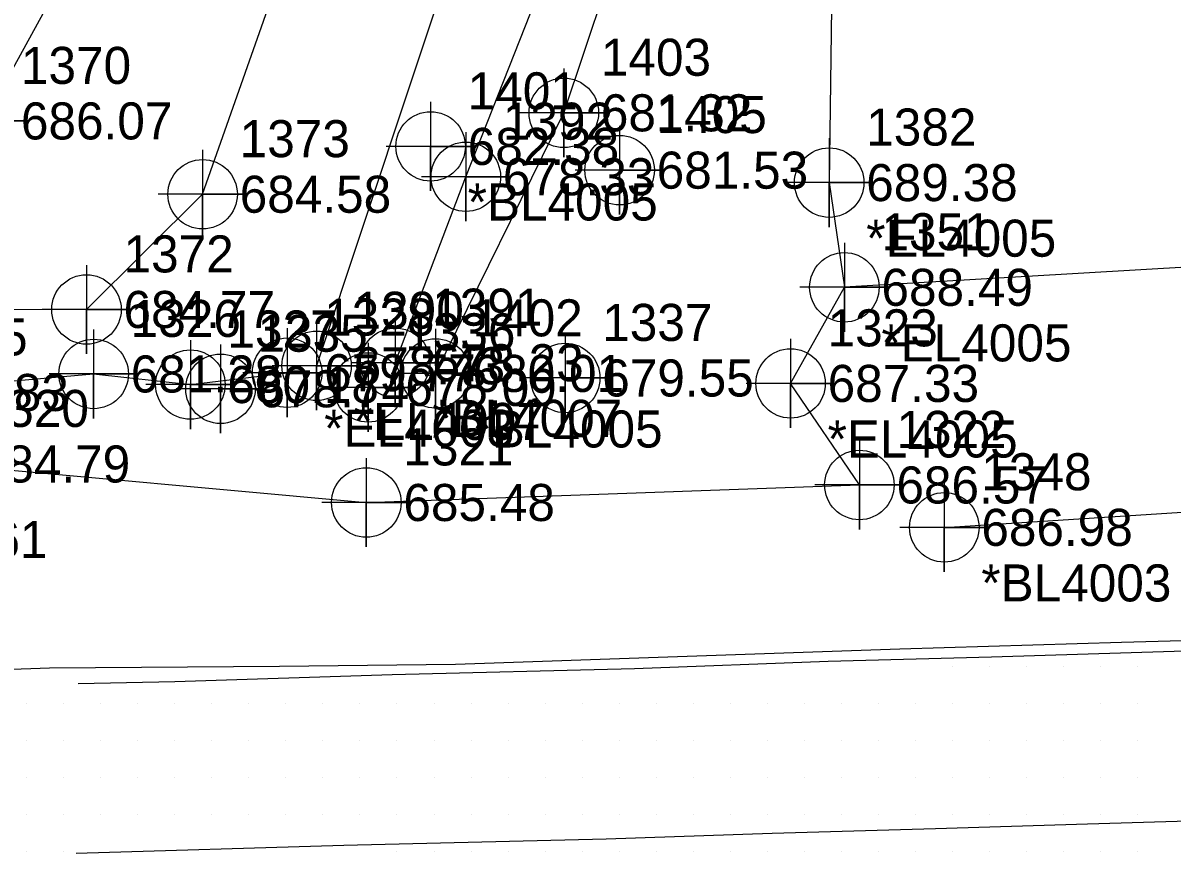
# Model space of a CAD drawing. Extents: x 1755643 to 1760494, y 736519 to 737621.
# Drawn here: x 1759066 to 1759143.6, y 737021.1 to 737077.2 of the extents above; entities that cross this region are included whole.
import ezdxf

# ---------------------------------------------------------------- set-up
doc = ezdxf.new("R2010")
doc.units = 0
for name, color, linetype in [('Exist Horizontal Alignment Curve and Spiral Data', 7, 'Continuous'), ('Exist Horizontal Alignment Direction Label', 7, 'Continuous'), ('Exist Roads EOT', 7, 'Continuous'), ('Exist Utilities Sanitary Sewer UG Line', 7, 'Continuous'), ('Old_Level_1', 7, 'Continuous'), ('Old_Level_10', 7, 'Continuous'), ('Old_Level_2', 7, 'Continuous'), ('Old_Level_3', 7, 'Continuous'), ('Prop Conc 5in Monolithic Keyed In Island', 7, 'Continuous'), ('Prop Dimension', 7, 'Continuous'), ('Prop EOT Dash', 7, 'Continuous'), ('Prop Horizontal Alignment Direction Label', 7, 'Continuous'), ('Prop Horizontal Alignment Station Label', 7, 'Continuous'), ('Prop Horizontal Alignment Tick Label', 7, 'Continuous'), ('Prop Horizontal Alignment Tick Large', 7, 'Continuous'), ('Prop Horizontal Alignment Tick Small', 7, 'Continuous'), ('Prop Lane Lines', 7, 'Continuous'), ('Prop Paved Shoulder', 7, 'Continuous'), ('Prop Superelevation Label', 7, 'Continuous'), ('Prop Terminator CELL', 7, 'Continuous'), ('Scratch_Level_1', 7, 'Continuous'), ('Scratch_Level_2', 7, 'Continuous'), ('Scratch_Level_5', 7, 'Continuous'), ('Scratch_Level_9', 7, 'Continuous')]:
    doc.layers.add(name, color=color, linetype=linetype)

msp = doc.modelspace()

# ---------------------------------------------------------------- linework, layer by layer
at = {"layer": 'Exist Horizontal Alignment Curve and Spiral Data'}
for points in [[(1759106.275, 737070.227), (1759106.275, 737064.227), (1759106.275, 737067.227), (1759109.275, 737067.227), (1759103.275, 737067.227)], [(1759102.603, 737056.204), (1759102.603, 737050.204), (1759102.603, 737053.204), (1759105.603, 737053.204), (1759099.603, 737053.204)], [(1759079.336, 737055.474), (1759079.336, 737049.474), (1759079.336, 737052.474), (1759082.336, 737052.474), (1759076.336, 737052.474)]]:
    msp.add_lwpolyline(points, dxfattribs=at)
for centre in [(1759106.275, 737067.227), (1759102.603, 737053.204), (1759079.336, 737052.474)]:
    msp.add_circle(centre, 2.344, dxfattribs=at)
at = {"layer": 'Old_Level_10'}
for points in [[(1759070.776, 737056.475), (1759070.776, 737050.475), (1759070.776, 737053.475), (1759073.776, 737053.475), (1759067.776, 737053.475)], [(1759083.837, 737056.56), (1759083.837, 737050.56), (1759083.837, 737053.56), (1759086.837, 737053.56), (1759080.837, 737053.56)], [(1759077.303, 737055.758), (1759077.303, 737049.758), (1759077.303, 737052.758), (1759080.303, 737052.758), (1759074.303, 737052.758)], [(1759128.188, 737046.125), (1759128.188, 737040.125), (1759128.188, 737043.125), (1759131.188, 737043.125), (1759125.188, 737043.125)]]:
    msp.add_lwpolyline(points, dxfattribs=at)
for centre in [(1759070.776, 737053.475), (1759083.837, 737053.56), (1759077.303, 737052.758), (1759128.188, 737043.125)]:
    msp.add_circle(centre, 2.344, dxfattribs=at)
at = {"layer": 'Prop Dimension'}
msp.add_line((1759128.188, 737043.125), (1759176.605, 737046.242), dxfattribs=at)
msp.add_lwpolyline([(1759031.302, 737046.485), (1759056.382, 737052.226), (1759070.776, 737053.475), (1759077.303, 737052.758), (1759083.837, 737053.56)], dxfattribs=at)
at = {"layer": 'Prop Horizontal Alignment Station Label'}
msp.add_lwpolyline([(1759089.307, 737055.567), (1759089.307, 737049.567), (1759089.307, 737052.567), (1759092.307, 737052.567), (1759086.307, 737052.567)], dxfattribs=at)
msp.add_circle((1759089.307, 737052.567), 2.344, dxfattribs=at)
at = {"layer": 'Prop Horizontal Alignment Tick Small'}
for points in [[(1759095.896, 737069.783), (1759095.896, 737063.783), (1759095.896, 737066.783), (1759098.896, 737066.783), (1759092.896, 737066.783)], [(1759085.823, 737057.025), (1759085.823, 737051.025), (1759085.823, 737054.025), (1759088.823, 737054.025), (1759082.823, 737054.025)], [(1759091.129, 737057.232), (1759091.129, 737051.232), (1759091.129, 737054.232), (1759094.129, 737054.232), (1759088.129, 737054.232)]]:
    msp.add_lwpolyline(points, dxfattribs=at)
for centre in [(1759095.896, 737066.783), (1759085.823, 737054.025), (1759091.129, 737054.232)]:
    msp.add_circle(centre, 2.344, dxfattribs=at)
at = {"layer": 'Prop Lane Lines'}
for points in [[(1759102.509, 737074.095), (1759102.509, 737068.095), (1759102.509, 737071.095), (1759105.509, 737071.095), (1759099.509, 737071.095)], [(1759063.368, 737073.548), (1759063.368, 737067.548), (1759063.368, 737070.548), (1759066.368, 737070.548), (1759060.368, 737070.548)], [(1759093.521, 737071.829), (1759093.521, 737065.829), (1759093.521, 737068.829), (1759096.521, 737068.829), (1759090.521, 737068.829)], [(1759120.419, 737069.387), (1759120.419, 737063.387), (1759120.419, 737066.387), (1759123.419, 737066.387), (1759117.419, 737066.387)], [(1759078.132, 737068.603), (1759078.132, 737062.603), (1759078.132, 737065.603), (1759081.132, 737065.603), (1759075.132, 737065.603)], [(1759121.445, 737062.322), (1759121.445, 737056.322), (1759121.445, 737059.322), (1759124.445, 737059.322), (1759118.445, 737059.322)], [(1759070.291, 737060.826), (1759070.291, 737054.826), (1759070.291, 737057.826), (1759073.291, 737057.826), (1759067.291, 737057.826)], [(1759093.85, 737056.511), (1759093.85, 737050.511), (1759093.85, 737053.511), (1759096.85, 737053.511), (1759090.85, 737053.511)], [(1759117.814, 737055.836), (1759117.814, 737049.836), (1759117.814, 737052.836), (1759120.814, 737052.836), (1759114.814, 737052.836)], [(1759122.458, 737048.984), (1759122.458, 737042.984), (1759122.458, 737045.984), (1759125.458, 737045.984), (1759119.458, 737045.984)], [(1759089.18, 737047.802), (1759089.18, 737041.802), (1759089.18, 737044.802), (1759092.18, 737044.802), (1759086.18, 737044.802)]]:
    msp.add_lwpolyline(points, dxfattribs=at)
for centre in [(1759102.509, 737071.095), (1759093.521, 737068.829), (1759120.419, 737066.387), (1759078.132, 737065.603), (1759121.445, 737059.322), (1759070.291, 737057.826), (1759093.85, 737053.511), (1759117.814, 737052.836), (1759122.458, 737045.984), (1759089.18, 737044.802)]:
    msp.add_circle(centre, 2.344, dxfattribs=at)
at = {"layer": 'Prop Terminator CELL'}
for points in [[(1759091.129, 737054.232), (1759095.896, 737066.783), (1759106.108, 737092.633), (1759116.257, 737109.006), (1759126.282, 737133.12), (1759139.374, 737163.771)], [(1759129.426, 737158.51), (1759116.04, 737134.286), (1759110.504, 737114.906), (1759098.55, 737092.322), (1759085.823, 737054.025)]]:
    msp.add_lwpolyline(points, dxfattribs=at)
at = {"layer": 'Scratch_Level_1'}
msp.add_lwpolyline([(1759245.745, 737039.347), (1759243.901, 737039.092), (1759228.947, 737038.55), (1759213.991, 737037.986), (1759199.029, 737037.383), (1759184.081, 737036.787), (1759169.113, 737036.293), (1759154.142, 737035.742), (1759140.158, 737035.361), (1759125.179, 737034.912), (1759110.187, 737034.391), (1759095.208, 737033.867), (1759083.321, 737033.73), (1759067.799, 737033.624), (1759060.797, 737033.37)], dxfattribs=at)
at = {"layer": 'Scratch_Level_2'}
for p, q in [((1759128.75, 737033.75), (1759128.75, 737033.75)), ((1759131.25, 737033.75), (1759131.25, 737033.75)), ((1759133.75, 737033.75), (1759133.75, 737033.75)), ((1759136.25, 737033.75), (1759136.25, 737033.75)), ((1759138.75, 737033.75), (1759138.75, 737033.75)), ((1759141.25, 737033.75), (1759141.25, 737033.75)), ((1759066.25, 737031.25), (1759066.25, 737031.25)), ((1759068.75, 737031.25), (1759068.75, 737031.25)), ((1759071.25, 737031.25), (1759071.25, 737031.25)), ((1759073.75, 737031.25), (1759073.75, 737031.25)), ((1759076.25, 737031.25), (1759076.25, 737031.25)), ((1759078.75, 737031.25), (1759078.75, 737031.25)), ((1759081.25, 737031.25), (1759081.25, 737031.25)), ((1759083.75, 737031.25), (1759083.75, 737031.25)), ((1759086.25, 737031.25), (1759086.25, 737031.25)), ((1759088.75, 737031.25), (1759088.75, 737031.25)), ((1759091.25, 737031.25), (1759091.25, 737031.25)), ((1759093.75, 737031.25), (1759093.75, 737031.25)), ((1759096.25, 737031.25), (1759096.25, 737031.25)), ((1759098.75, 737031.25), (1759098.75, 737031.25)), ((1759101.25, 737031.25), (1759101.25, 737031.25)), ((1759103.75, 737031.25), (1759103.75, 737031.25)), ((1759106.25, 737031.25), (1759106.25, 737031.25)), ((1759108.75, 737031.25), (1759108.75, 737031.25)), ((1759111.25, 737031.25), (1759111.25, 737031.25)), ((1759113.75, 737031.25), (1759113.75, 737031.25)), ((1759116.25, 737031.25), (1759116.25, 737031.25)), ((1759118.75, 737031.25), (1759118.75, 737031.25)), ((1759121.25, 737031.25), (1759121.25, 737031.25)), ((1759123.75, 737031.25), (1759123.75, 737031.25)), ((1759126.25, 737031.25), (1759126.25, 737031.25)), ((1759128.75, 737031.25), (1759128.75, 737031.25)), ((1759131.25, 737031.25), (1759131.25, 737031.25)), ((1759133.75, 737031.25), (1759133.75, 737031.25)), ((1759136.25, 737031.25), (1759136.25, 737031.25)), ((1759138.75, 737031.25), (1759138.75, 737031.25)), ((1759141.25, 737031.25), (1759141.25, 737031.25)), ((1759066.25, 737028.75), (1759066.25, 737028.75)), ((1759068.75, 737028.75), (1759068.75, 737028.75)), ((1759071.25, 737028.75), (1759071.25, 737028.75)), ((1759073.75, 737028.75), (1759073.75, 737028.75)), ((1759076.25, 737028.75), (1759076.25, 737028.75)), ((1759078.75, 737028.75), (1759078.75, 737028.75)), ((1759081.25, 737028.75), (1759081.25, 737028.75)), ((1759083.75, 737028.75), (1759083.75, 737028.75)), ((1759086.25, 737028.75), (1759086.25, 737028.75)), ((1759088.75, 737028.75), (1759088.75, 737028.75)), ((1759091.25, 737028.75), (1759091.25, 737028.75)), ((1759093.75, 737028.75), (1759093.75, 737028.75)), ((1759096.25, 737028.75), (1759096.25, 737028.75)), ((1759098.75, 737028.75), (1759098.75, 737028.75)), ((1759101.25, 737028.75), (1759101.25, 737028.75)), ((1759103.75, 737028.75), (1759103.75, 737028.75)), ((1759106.25, 737028.75), (1759106.25, 737028.75)), ((1759108.75, 737028.75), (1759108.75, 737028.75)), ((1759111.25, 737028.75), (1759111.25, 737028.75)), ((1759113.75, 737028.75), (1759113.75, 737028.75)), ((1759116.25, 737028.75), (1759116.25, 737028.75)), ((1759118.75, 737028.75), (1759118.75, 737028.75)), ((1759121.25, 737028.75), (1759121.25, 737028.75)), ((1759123.75, 737028.75), (1759123.75, 737028.75)), ((1759126.25, 737028.75), (1759126.25, 737028.75)), ((1759128.75, 737028.75), (1759128.75, 737028.75)), ((1759131.25, 737028.75), (1759131.25, 737028.75)), ((1759133.75, 737028.75), (1759133.75, 737028.75)), ((1759136.25, 737028.75), (1759136.25, 737028.75)), ((1759138.75, 737028.75), (1759138.75, 737028.75)), ((1759141.25, 737028.75), (1759141.25, 737028.75)), ((1759066.25, 737026.25), (1759066.25, 737026.25)), ((1759068.75, 737026.25), (1759068.75, 737026.25)), ((1759071.25, 737026.25), (1759071.25, 737026.25)), ((1759073.75, 737026.25), (1759073.75, 737026.25)), ((1759076.25, 737026.25), (1759076.25, 737026.25)), ((1759078.75, 737026.25), (1759078.75, 737026.25)), ((1759081.25, 737026.25), (1759081.25, 737026.25)), ((1759083.75, 737026.25), (1759083.75, 737026.25)), ((1759086.25, 737026.25), (1759086.25, 737026.25)), ((1759088.75, 737026.25), (1759088.75, 737026.25)), ((1759091.25, 737026.25), (1759091.25, 737026.25)), ((1759093.75, 737026.25), (1759093.75, 737026.25)), ((1759096.25, 737026.25), (1759096.25, 737026.25)), ((1759098.75, 737026.25), (1759098.75, 737026.25)), ((1759101.25, 737026.25), (1759101.25, 737026.25)), ((1759103.75, 737026.25), (1759103.75, 737026.25)), ((1759106.25, 737026.25), (1759106.25, 737026.25)), ((1759108.75, 737026.25), (1759108.75, 737026.25)), ((1759111.25, 737026.25), (1759111.25, 737026.25)), ((1759113.75, 737026.25), (1759113.75, 737026.25)), ((1759116.25, 737026.25), (1759116.25, 737026.25)), ((1759118.75, 737026.25), (1759118.75, 737026.25)), ((1759121.25, 737026.25), (1759121.25, 737026.25)), ((1759123.75, 737026.25), (1759123.75, 737026.25)), ((1759126.25, 737026.25), (1759126.25, 737026.25)), ((1759128.75, 737026.25), (1759128.75, 737026.25)), ((1759131.25, 737026.25), (1759131.25, 737026.25)), ((1759133.75, 737026.25), (1759133.75, 737026.25)), ((1759136.25, 737026.25), (1759136.25, 737026.25)), ((1759138.75, 737026.25), (1759138.75, 737026.25)), ((1759141.25, 737026.25), (1759141.25, 737026.25)), ((1759066.25, 737023.75), (1759066.25, 737023.75)), ((1759068.75, 737023.75), (1759068.75, 737023.75)), ((1759071.25, 737023.75), (1759071.25, 737023.75)), ((1759073.75, 737023.75), (1759073.75, 737023.75)), ((1759076.25, 737023.75), (1759076.25, 737023.75)), ((1759078.75, 737023.75), (1759078.75, 737023.75)), ((1759081.25, 737023.75), (1759081.25, 737023.75)), ((1759083.75, 737023.75), (1759083.75, 737023.75)), ((1759086.25, 737023.75), (1759086.25, 737023.75)), ((1759088.75, 737023.75), (1759088.75, 737023.75)), ((1759091.25, 737023.75), (1759091.25, 737023.75)), ((1759093.75, 737023.75), (1759093.75, 737023.75)), ((1759096.25, 737023.75), (1759096.25, 737023.75)), ((1759098.75, 737023.75), (1759098.75, 737023.75)), ((1759101.25, 737023.75), (1759101.25, 737023.75)), ((1759103.75, 737023.75), (1759103.75, 737023.75)), ((1759106.25, 737023.75), (1759106.25, 737023.75)), ((1759108.75, 737023.75), (1759108.75, 737023.75)), ((1759111.25, 737023.75), (1759111.25, 737023.75)), ((1759113.75, 737023.75), (1759113.75, 737023.75)), ((1759116.25, 737023.75), (1759116.25, 737023.75)), ((1759118.75, 737023.75), (1759118.75, 737023.75)), ((1759121.25, 737023.75), (1759121.25, 737023.75)), ((1759123.75, 737023.75), (1759123.75, 737023.75)), ((1759126.25, 737023.75), (1759126.25, 737023.75)), ((1759128.75, 737023.75), (1759128.75, 737023.75)), ((1759131.25, 737023.75), (1759131.25, 737023.75)), ((1759133.75, 737023.75), (1759133.75, 737023.75)), ((1759136.25, 737023.75), (1759136.25, 737023.75)), ((1759138.75, 737023.75), (1759138.75, 737023.75)), ((1759141.25, 737023.75), (1759141.25, 737023.75)), ((1759066.25, 737021.25), (1759066.25, 737021.25)), ((1759068.75, 737021.25), (1759068.75, 737021.25)), ((1759091.25, 737021.25), (1759091.25, 737021.25)), ((1759093.75, 737021.25), (1759093.75, 737021.25)), ((1759096.25, 737021.25), (1759096.25, 737021.25)), ((1759098.75, 737021.25), (1759098.75, 737021.25)), ((1759101.25, 737021.25), (1759101.25, 737021.25)), ((1759103.75, 737021.25), (1759103.75, 737021.25)), ((1759106.25, 737021.25), (1759106.25, 737021.25)), ((1759108.75, 737021.25), (1759108.75, 737021.25)), ((1759111.25, 737021.25), (1759111.25, 737021.25)), ((1759113.75, 737021.25), (1759113.75, 737021.25)), ((1759116.25, 737021.25), (1759116.25, 737021.25)), ((1759118.75, 737021.25), (1759118.75, 737021.25)), ((1759121.25, 737021.25), (1759121.25, 737021.25)), ((1759123.75, 737021.25), (1759123.75, 737021.25)), ((1759126.25, 737021.25), (1759126.25, 737021.25)), ((1759128.75, 737021.25), (1759128.75, 737021.25)), ((1759131.25, 737021.25), (1759131.25, 737021.25)), ((1759133.75, 737021.25), (1759133.75, 737021.25)), ((1759136.25, 737021.25), (1759136.25, 737021.25)), ((1759138.75, 737021.25), (1759138.75, 737021.25)), ((1759141.25, 737021.25), (1759141.25, 737021.25))]:
    msp.add_line(p, q, dxfattribs=at)
at = {"layer": 'Scratch_Level_5'}
for points in [[(1759264.346, 737038.157), (1759256.257, 737037.899), (1759245.167, 737037.58), (1759230.48, 737037.148), (1759220.483, 737036.889), (1759208.302, 737036.581), (1759197.58, 737036.227), (1759187.39, 737035.923), (1759169.715, 737035.522), (1759156.989, 737035.176), (1759143.698, 737034.757), (1759131.382, 737034.354), (1759120.362, 737034.067), (1759107.277, 737033.587), (1759090.927, 737033.176), (1759076.254, 737032.701), (1759069.724, 737032.565)], [(1759069.599, 737021.15), (1759087.665, 737021.687), (1759105.377, 737022.114), (1759116.561, 737022.489), (1759127.592, 737022.807), (1759137.847, 737023.125), (1759152.201, 737023.546), (1759173.118, 737024.162), (1759192.023, 737024.813), (1759212.987, 737025.408), (1759241.366, 737026.248), (1759257.052, 737026.718), (1759264.843, 737026.956)]]:
    msp.add_lwpolyline(points, dxfattribs=at)
at = {"layer": 'Scratch_Level_9'}
msp.add_line((1759175.335, 737062.514), (1759121.445, 737059.322), dxfattribs=at)
for points in [[(1759114.235, 737167.89), (1759096.366, 737128.921), (1759076.674, 737094.816), (1759063.368, 737070.548), (1759053.397, 737057.897), (1759070.291, 737057.826), (1759078.132, 737065.603), (1759087.493, 737092.167), (1759101.517, 737116.771), (1759113.495, 737140.742), (1759123.733, 737160.905)], [(1759156.089, 737163.588), (1759140.962, 737130.981), (1759127.495, 737105.578), (1759120.622, 737081.604), (1759120.419, 737066.387), (1759121.445, 737059.322)], [(1759093.85, 737053.511), (1759102.509, 737071.095), (1759106.711, 737083.664)], [(1759019.545, 737039.098), (1759054.939, 737042.312), (1759060.518, 737047.4), (1759089.18, 737044.802), (1759122.458, 737045.984), (1759117.814, 737052.836), (1759121.445, 737059.322)]]:
    msp.add_lwpolyline(points, dxfattribs=at)

# ---------------------------------------------------------------- texts
at = {"layer": 'Exist Horizontal Alignment Direction Label'}
for s, p in [('*BL4005', (1759096.021, 737063.829)), ('*EL4005', (1759122.919, 737061.387)), ('*EL4005', (1759123.945, 737054.322)), ('*BL4005', (1759096.35, 737048.511)), ('*EL4005', (1759120.314, 737047.836))]:
    msp.add_text(s, height=2.5, dxfattribs=at).set_placement(p)
at = {"layer": 'Exist Roads EOT'}
for s, p in [('1405', (1759108.775, 737069.727)), ('1337', (1759105.103, 737055.704)), ('1335', (1759081.836, 737054.974))]:
    msp.add_text(s, height=2.5, dxfattribs=at).set_placement(p)
at = {"layer": 'Exist Utilities Sanitary Sewer UG Line'}
for s, p in [('678.33', (1759098.396, 737065.533)), ('678.23', (1759093.629, 737052.982)), ('678.43', (1759088.323, 737052.775))]:
    msp.add_text(s, height=2.5, dxfattribs=at).set_placement(p)
at = {"layer": 'Old_Level_1'}
for s, p in [('1326', (1759073.276, 737055.975)), ('1328', (1759086.337, 737056.06)), ('1327', (1759079.803, 737055.258)), ('1325', (1759058.882, 737054.726)), ('1348', (1759130.688, 737045.625))]:
    msp.add_text(s, height=2.5, dxfattribs=at).set_placement(p)
at = {"layer": 'Old_Level_2'}
for s, p in [('681.28', (1759073.276, 737052.225)), ('679.77', (1759086.337, 737052.31)), ('680.18', (1759079.803, 737051.508)), ('683.83', (1759058.882, 737050.976)), ('686.98', (1759130.688, 737041.875))]:
    msp.add_text(s, height=2.5, dxfattribs=at).set_placement(p)
at = {"layer": 'Old_Level_3'}
for s, p in [('686.07', (1759065.868, 737069.298)), ('681.32', (1759105.009, 737069.845)), ('682.38', (1759096.021, 737067.579)), ('689.38', (1759122.919, 737065.137)), ('684.58', (1759080.632, 737064.353)), ('688.49', (1759123.945, 737058.072)), ('684.77', (1759072.791, 737056.576)), ('680.01', (1759096.35, 737052.261)), ('687.33', (1759120.314, 737051.586)), ('684.79', (1759063.018, 737046.15)), ('686.57', (1759124.958, 737044.734)), ('685.48', (1759091.68, 737043.552)), ('685.61', (1759057.439, 737041.062))]:
    msp.add_text(s, height=2.5, dxfattribs=at).set_placement(p)
at = {"layer": 'Prop Conc 5in Monolithic Keyed In Island'}
for s, p in [('1392', (1759098.396, 737069.283)), ('1391', (1759093.629, 737056.732)), ('1390', (1759088.323, 737056.525))]:
    msp.add_text(s, height=2.5, dxfattribs=at).set_placement(p)
at = {"layer": 'Prop EOT Dash'}
for s, p in [('1370', (1759065.868, 737073.048)), ('1403', (1759105.009, 737073.595)), ('1401', (1759096.021, 737071.329)), ('1382', (1759122.919, 737068.887)), ('1373', (1759080.632, 737068.103)), ('1351', (1759123.945, 737061.822)), ('1372', (1759072.791, 737060.326)), ('1402', (1759096.35, 737056.011)), ('1323', (1759120.314, 737055.336)), ('1320', (1759063.018, 737049.9)), ('1322', (1759124.958, 737048.484)), ('1321', (1759091.68, 737047.302))]:
    msp.add_text(s, height=2.5, dxfattribs=at).set_placement(p)
at = {"layer": 'Prop Horizontal Alignment Direction Label'}
for s, p in [('*EL4003', (1759086.337, 737048.56)), ('*BL4003', (1759130.688, 737038.125))]:
    msp.add_text(s, height=2.5, dxfattribs=at).set_placement(p)
at = {"layer": 'Prop Horizontal Alignment Tick Label'}
msp.add_text('1336', height=2.5, dxfattribs=at).set_placement((1759091.807, 737055.067))
at = {"layer": 'Prop Horizontal Alignment Tick Large'}
msp.add_text('678.09', height=2.5, dxfattribs=at).set_placement((1759091.807, 737051.317))
at = {"layer": 'Prop Paved Shoulder'}
for s, p in [('681.53', (1759108.775, 737065.977)), ('679.55', (1759105.103, 737051.954)), ('678.74', (1759081.836, 737051.224))]:
    msp.add_text(s, height=2.5, dxfattribs=at).set_placement(p)
at = {"layer": 'Prop Superelevation Label'}
for s, p in [('*EL4007', (1759088.323, 737049.025)), ('*BL4007', (1759093.629, 737049.232))]:
    msp.add_text(s, height=2.5, dxfattribs=at).set_placement(p)

doc.saveas('drawing.dxf')
